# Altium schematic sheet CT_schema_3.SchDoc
size 321 x 189 mm
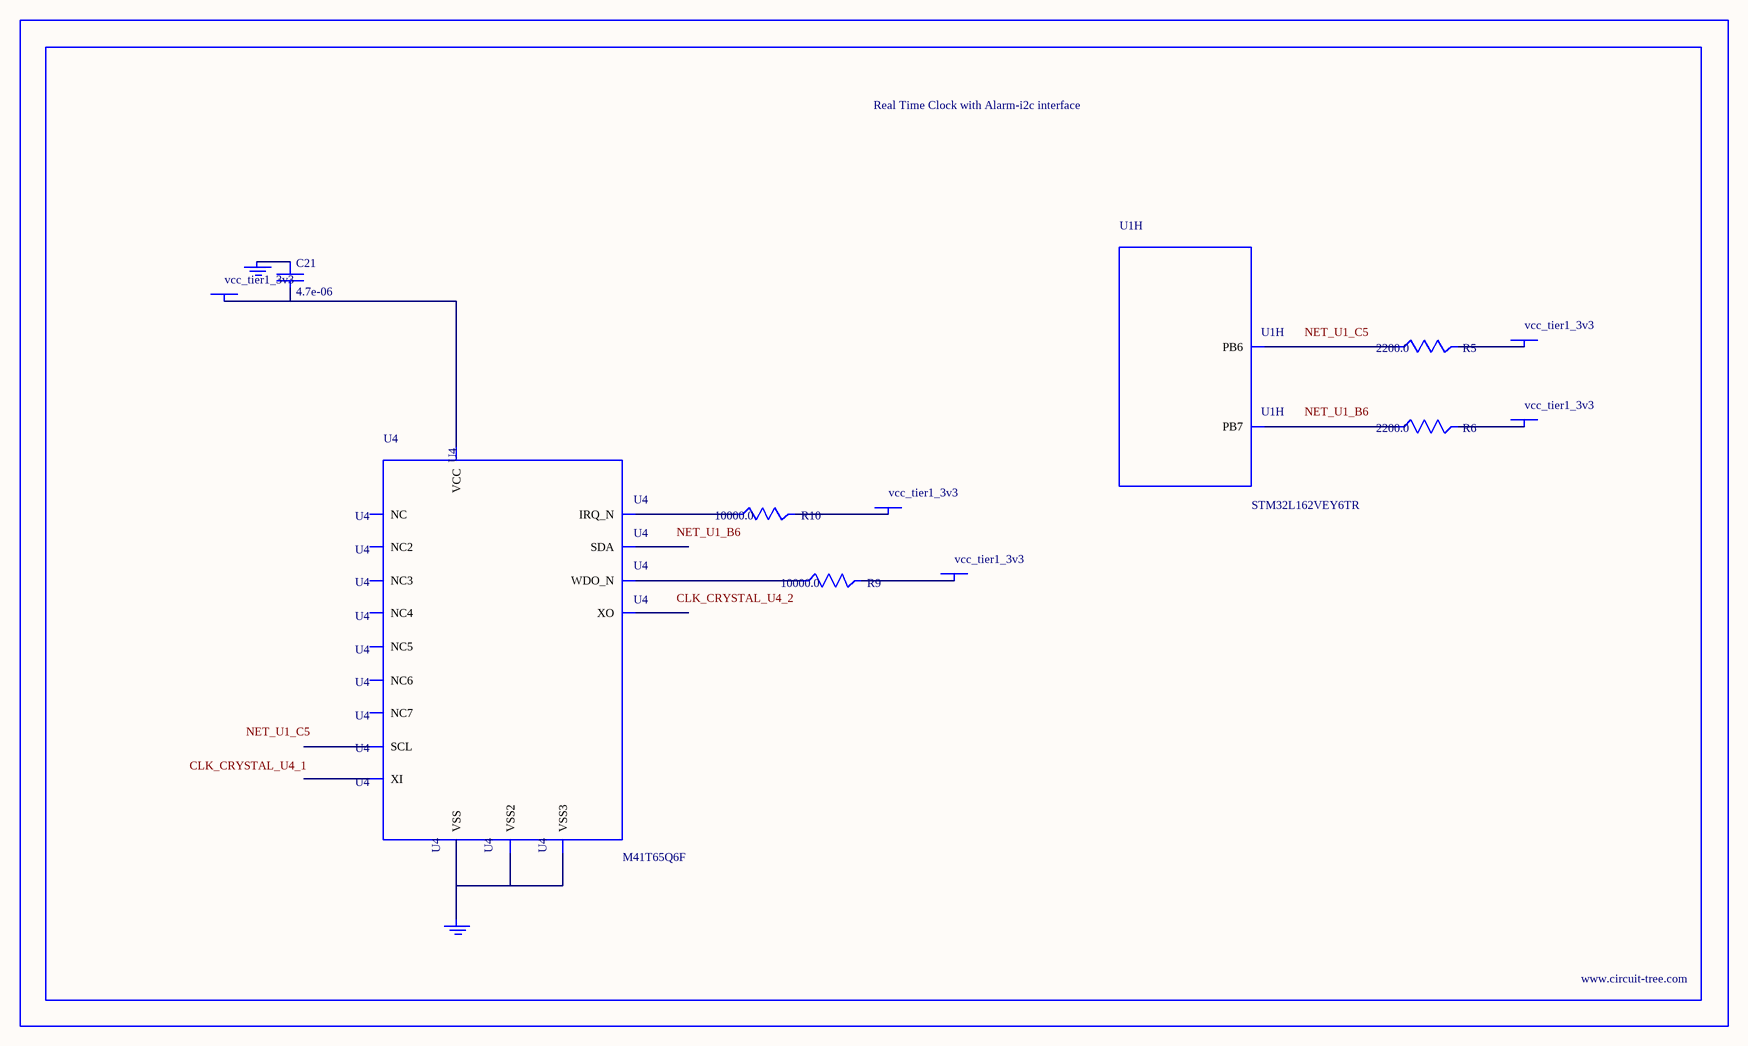
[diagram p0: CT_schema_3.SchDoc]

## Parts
BORDER2  (no value)
C21  4.7e-06  [C0805]
GND_INSTANCE_2_0  (no value)
GND_INSTANCE_2_1  (no value)
POWER_INSTANCE_2_0  vcc_tier1_3v3
POWER_INSTANCE_2_1  vcc_tier1_3v3
POWER_INSTANCE_2_2  vcc_tier1_3v3
POWER_INSTANCE_2_3  vcc_tier1_3v3
POWER_INSTANCE_2_4  vcc_tier1_3v3
R5  2200.0  [R0603]
R6  2200.0  [R0603]
R9  10000.0  [R0603]
R10  10000.0  [R0603]
U1  STM32L162VEY6TR  [WLCSP104]  (part H of 9)
U4  M41T65Q6F  [M41T65_QFN-16]

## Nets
NetC21_1: C21.1 GND_INSTANCE_2_0.0(GND)
NetC21_2: C21.2 POWER_INSTANCE_2_2.0(PWR) U4.14(VCC)
NetGND_INSTANCE_2_1_0: GND_INSTANCE_2_1.0(GND) U4.3(VSS) U4.5(VSS2) U4.17(VSS3)
NetPOWER_INSTANCE_2_0_0: POWER_INSTANCE_2_0.0(PWR) R9.2
NetPOWER_INSTANCE_2_1_0: POWER_INSTANCE_2_1.0(PWR) R10.2
NetPOWER_INSTANCE_2_3_0: POWER_INSTANCE_2_3.0(PWR) R5.2
NetPOWER_INSTANCE_2_4_0: POWER_INSTANCE_2_4.0(PWR) R6.2
NetR5_1: R5.1 U1.C5(PB6)
NetR6_1: R6.1 U1.B6(PB7)
NetR9_1: R9.1 U4.4(WDO_N)
NetR10_1: R10.1 U4.11(IRQ_N)

Not connected (* = marked no-connect by the designer): U4 1(XI) 2(XO) 6(NC) 7(NC2) 8(NC3) 9(SDA) 10(SCL) 12(NC4) 13(NC5) 15(NC6) 16(NC7)

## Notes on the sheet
- Labels drawn without touching a wire or pin: CLK_CRYSTAL_U4_1, CLK_CRYSTAL_U4_2, NET_U1_B6, NET_U1_C5

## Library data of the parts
BORDER2 = BORDER_PAGE2
C21 = C0805C475K4RACTU
GND_INSTANCE_2_0 GND_INSTANCE_2_1 = GND
POWER_INSTANCE_2_0-POWER_INSTANCE_2_4 = PWR
R5 R6 = RC0603JR-072K2L
R9 R10 = RC0603JR-0710KL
